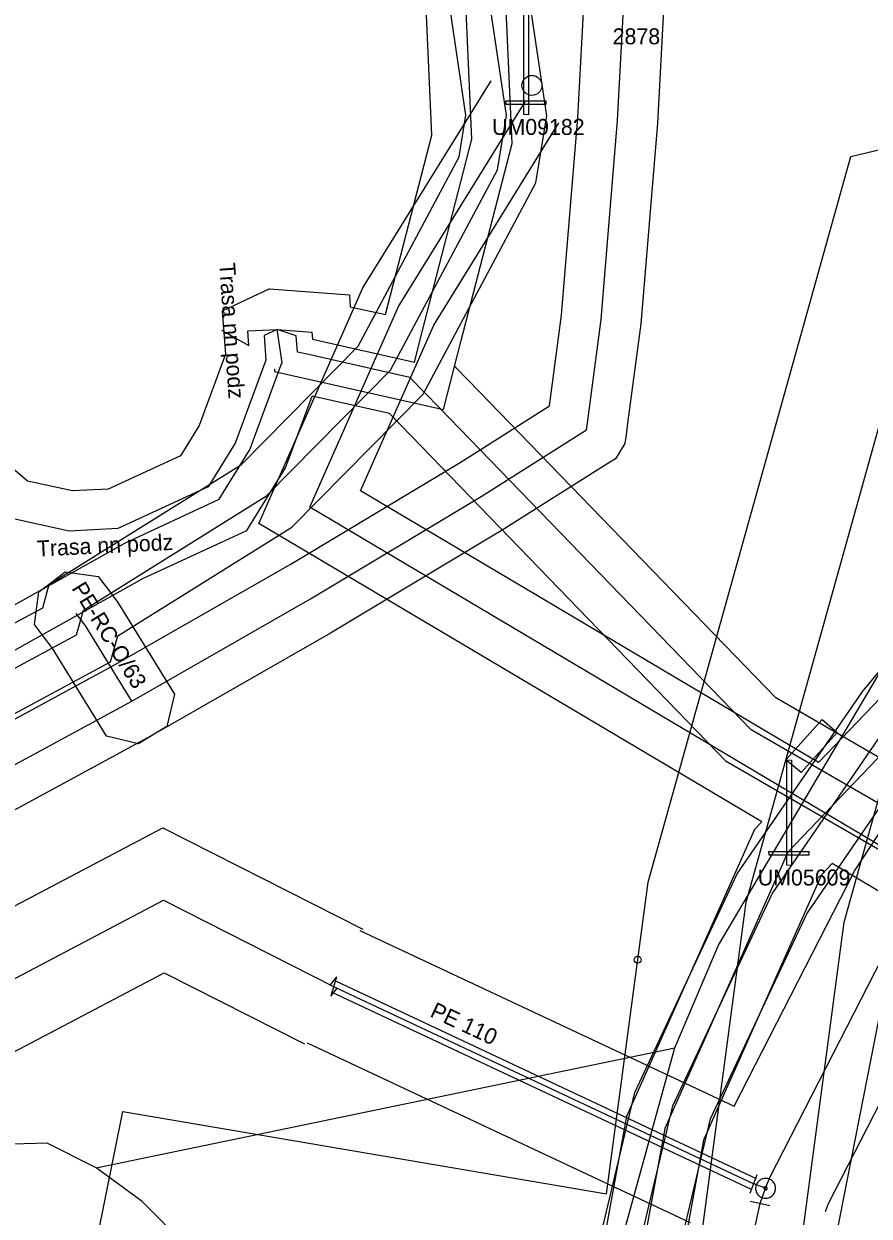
# Model space of a CAD drawing. Extents: x -762993 to -761845, y -975230 to -974501.
# Drawn here: x -762318.78 to -762297.6, y -975033.65 to -975003.77 of the extents above; entities that cross this region are included whole.
import ezdxf

# ---------------------------------------------------------------- set-up
doc = ezdxf.new("R2010")
doc.units = 0
for name, color, linetype in [('IS_CETIN_OP', 7, 'Continuous'), ('IS_CETIN_podzem metalika zam', 7, 'Continuous'), ('IS_CETIN_podzem out of order', 7, 'Continuous'), ('IS_CEZ-D_anotace', 7, 'Continuous'), ('IS_CEZ-D_el vedeni NN podzem', 7, 'Continuous'), ('IS_CEZ-D_OP', 7, 'Continuous'), ('IS_CEZ-T_parovod', 7, 'Continuous'), ('IS_CEZ-T_parovod OP', 7, 'Continuous'), ('IS_DPmUL_OP', 7, 'Continuous'), ('IS_DPmUL_trakce anotace', 7, 'Continuous'), ('IS_DPmUL_trakce stozary', 7, 'Continuous'), ('IS_DPmUL_VO lampy', 7, 'Continuous'), ('IS_DPmUL_VO lampy anotace', 7, 'Continuous'), ('IS_DPmUL_VO vedeni podzem', 7, 'Continuous'), ('IS_GASNET_plyn NTL anotace', 7, 'Continuous'), ('IS_GASNET_plyn NTL pripojky', 7, 'Continuous'), ('IS_GASNET_plyn NTL rad', 7, 'Continuous'), ('IS_GASNET_plyn OP', 7, 'Continuous'), ('IS_SCVK_vodovod anotace', 7, 'Continuous'), ('IS_SCVK_vodovod chranicka', 7, 'Continuous'), ('IS_SCVK_vodovod OP', 7, 'Continuous'), ('IS_SCVK_vodovod privadec', 7, 'Continuous'), ('IS_SCVK_vodovod znaky', 7, 'Continuous'), ('IS_T-Mobile_OP', 7, 'Continuous'), ('IS_T-Mobile_podzem optika', 7, 'Continuous')]:
    doc.layers.add(name, color=color, linetype=linetype)

msp = doc.modelspace()

# ---------------------------------------------------------------- linework, layer by layer
at = {"layer": 'IS_CETIN_OP'}
for points in [[(-762333.143, -975068.542), (-762327.185, -975070.257), (-762325.869, -975070.135), (-762319.571, -975070.861), (-762312.657, -975072.148), (-762308.168, -975050.829), (-762306.083, -975041.38), (-762305.481, -975039.001), (-762303.469, -975030.548), (-762300.901, -975025.071), (-762297.758, -975020.495), (-762293.905, -975015.874), (-762285.788, -975009.313), (-762278.568, -975006.279), (-762273.774, -975005.065), (-762267.42, -975003.752), (-762256.598, -975003.579), (-762252.471, -975004.243)], [(-762333.697, -975070.464), (-762327.375, -975072.283), (-762325.891, -975072.145), (-762319.869, -975072.839), (-762311.103, -975074.472), (-762306.212, -975051.251), (-762304.137, -975041.84), (-762303.539, -975039.479), (-762301.571, -975031.212), (-762299.159, -975026.069), (-762296.162, -975021.705), (-762292.495, -975017.306), (-762284.752, -975011.047), (-762277.932, -975008.181), (-762273.326, -975007.015), (-762267.2, -975005.748), (-762256.742, -975005.581), (-762252.789, -975006.217)]]:
    msp.add_lwpolyline(points, dxfattribs=at)
at = {"layer": 'IS_CETIN_podzem metalika zam'}
msp.add_lwpolyline([(-762333.42, -975069.503), (-762327.28, -975071.27), (-762325.88, -975071.14), (-762319.72, -975071.85), (-762311.88, -975073.31), (-762307.19, -975051.04), (-762305.11, -975041.61), (-762304.51, -975039.24), (-762302.52, -975030.88), (-762300.03, -975025.57), (-762296.96, -975021.1), (-762293.2, -975016.59), (-762285.27, -975010.18), (-762278.25, -975007.23), (-762273.55, -975006.04), (-762267.31, -975004.75), (-762256.67, -975004.58), (-762252.63, -975005.23)], dxfattribs=at)
at = {"layer": 'IS_CETIN_podzem out of order'}
for points in [[(-762302.47, -975029.43), (-762301.37, -975026.86), (-762297.29, -975019.96), (-762293.71, -975015.73), (-762290.26, -975012.31), (-762286.4, -975009.38), (-762280.32, -975006.03), (-762275.63, -975004.71), (-762266.26, -975003.66), (-762260.97, -975004.16), (-762250.2, -975005.66)], [(-762314.94, -975039.44), (-762305.75, -975041.48), (-762300.55, -975042.65), (-762300.16, -975040.36), (-762298.53, -975034.72), (-762296.75, -975025.67), (-762290.69, -975018.58), (-762286.29, -975015.28), (-762283.37, -975012.48), (-762276.83, -975008.96), (-762270.07, -975007.94), (-762262.86, -975007.55), (-762258.26, -975007.97), (-762258.37, -975010.02)], [(-762316.97, -975032.44), (-762302.47, -975029.43)], [(-762314.72, -975038.47), (-762313.26, -975038.76), (-762305.52, -975040.49), (-762302.47, -975029.43)], [(-762316.97, -975032.44), (-762318.2, -975031.82), (-762319.64, -975031.86), (-762321.84, -975032.66), (-762325.75, -975034.84), (-762334.32, -975039.88), (-762342.38, -975044.44), (-762350.45, -975049.19)], [(-762314.72, -975038.47), (-762314.35, -975036), (-762314.74, -975034.37), (-762315.82, -975033.28), (-762316.97, -975032.44)]]:
    msp.add_lwpolyline(points, dxfattribs=at)
at = {"layer": 'IS_CEZ-D_el vedeni NN podzem'}
for points in [[(-762312.434, -975011.429), (-762311.562, -975011.492), (-762311.55, -975011.669), (-762308.991, -975012.245), (-762308.787, -975011.452), (-762307.552, -975006.66), (-762307.854, -974999.844), (-762312.234, -974993.249), (-762317.513, -974989.187), (-762333.367, -974983.038), (-762339.038, -974981.25), (-762354.832, -974975.823), (-762355.035, -974975.753), (-762355.226, -974976.23), (-762356.629, -974979.736), (-762357.615, -974982.215), (-762357.804, -974982.149)], [(-762323.24, -975032.631), (-762327.897, -975023.324), (-762326.508, -975022.51), (-762316.256, -975016.781), (-762313.888, -975015.684), (-762313.128, -975014.455), (-762313.114, -975014.417), (-762312.341, -975012.334), (-762312.311, -975012.253), (-762312.434, -975011.429)], [(-762312.434, -975011.429), (-762312.761, -975011.582), (-762312.716, -975012.195), (-762313.489, -975014.278), (-762314.166, -975015.372), (-762316.424, -975016.419), (-762317.643, -975016.479), (-762319.16, -975016.149), (-762319.611, -975015.754), (-762320.71, -975014.965), (-762320.816, -975013.314), (-762320.212, -975013.263), (-762320.229, -975013.064)], [(-762313.829, -975011.448), (-762313.143, -975011.83), (-762313.169, -975011.461), (-762312.434, -975011.429)], [(-762266.642, -975017.146), (-762269.935, -975017.363), (-762272.799, -975018.022), (-762274.441, -975018.54), (-762276.825, -975019.952), (-762278.883, -975021.862), (-762280.371, -975023.677), (-762281.857, -975025.781), (-762283.232, -975030.127), (-762294.247, -975025.106), (-762300.557, -975021.459), (-762308.359, -975013.401), (-762309.107, -975012.628), (-762311.684, -975012.049), (-762311.927, -975011.994), (-762311.958, -975011.586), (-762312.434, -975011.429)]]:
    msp.add_lwpolyline(points, dxfattribs=at)
at = {"layer": 'IS_CEZ-D_OP'}
for points in [[(-762312.622, -975010.413), (-762310.623, -975010.557), (-762310.603, -975010.857), (-762309.718, -975011.056), (-762308.558, -975006.555), (-762308.841, -975000.166), (-762312.975, -974993.94), (-762318.009, -974990.067), (-762333.698, -974983.982), (-762339.351, -974982.2), (-762354.46, -974977.008), (-762355.7, -974980.107), (-762357.04, -974983.475), (-762358.93, -974982.815)], [(-762312.506, -975012.426), (-762312.501, -975012.427), (-762312.497, -975012.481), (-762308.264, -975013.434), (-762307.819, -975011.701), (-762306.546, -975006.765), (-762306.867, -974999.522), (-762311.493, -974992.558), (-762311.896, -974992.247)], [(-762312.622, -975010.413), (-762313.809, -975010.968), (-762313.729, -975012.051), (-762314.392, -975013.837), (-762314.859, -975014.591), (-762316.668, -975015.43), (-762317.56, -975015.474), (-762318.695, -975015.227), (-762318.989, -975014.97), (-762319.742, -975014.429), (-762319.755, -975014.228), (-762319.13, -975014.175), (-762319.233, -975012.979)], [(-762210.784, -975019.48), (-762216.14, -975019.152), (-762233.918, -975018.301), (-762252.803, -975016.92), (-762257.758, -975016.55), (-762262.733, -975016.178), (-762264.701, -975016.162), (-762266.671, -975016.146), (-762270.081, -975016.37), (-762273.062, -975017.056), (-762274.852, -975017.621), (-762277.427, -975019.146), (-762279.613, -975021.175), (-762281.167, -975023.071), (-762282.764, -975025.331), (-762283.845, -975028.749), (-762293.788, -975024.216), (-762299.936, -975020.663), (-762307.64, -975012.706), (-762307.985, -975012.349)], [(-762321.902, -975033.07), (-762326.584, -975023.714), (-762326.011, -975023.378), (-762315.801, -975017.672), (-762313.195, -975016.465), (-762312.224, -975014.895), (-762312.176, -975014.764), (-762311.559, -975013.102)], [(-762209.615, -975021.555), (-762216.248, -975021.15), (-762234.038, -975020.297), (-762252.951, -975018.914), (-762257.906, -975018.544), (-762262.815, -975018.178), (-762264.717, -975018.162), (-762266.613, -975018.146), (-762269.789, -975018.356), (-762272.536, -975018.988), (-762274.03, -975019.459), (-762276.223, -975020.758), (-762278.153, -975022.549), (-762279.575, -975024.283), (-762280.95, -975026.231), (-762282.619, -975031.505), (-762294.706, -975025.996), (-762301.178, -975022.255), (-762309.078, -975014.096), (-762309.618, -975013.538), (-762311.559, -975013.102)]]:
    msp.add_lwpolyline(points, dxfattribs=at)
at = {"layer": 'IS_CEZ-T_parovod'}
for points in [[(-762300.68, -975025.78), (-762296.04, -975009.18), (-762277.86, -975004.82)], [(-762319.25, -975058.25), (-762314.33, -975033.9), (-762302.04, -975035.99), (-762300.68, -975025.78)]]:
    msp.add_lwpolyline(points, dxfattribs=at)
at = {"layer": 'IS_CEZ-T_parovod OP'}
for points in [[(-762303.135, -975025.276), (-762298.052, -975007.092), (-762280.855, -975002.967)], [(-762298.225, -975026.284), (-762294.028, -975011.268), (-762278.275, -975007.49)], [(-762321.7, -975057.755), (-762316.3, -975031.029), (-762304.176, -975033.091), (-762303.135, -975025.276)], [(-762316.8, -975058.745), (-762312.36, -975036.771), (-762299.904, -975038.889), (-762298.225, -975026.284)]]:
    msp.add_lwpolyline(points, dxfattribs=at)
at = {"layer": 'IS_DPmUL_OP'}
for p, q in [((-762286.053, -975008.896), (-762298.867, -975022.284)), ((-762300.286, -975023.767), (-762300.474, -975023.963)), ((-762298.521, -975024.815), (-762298.788, -975025.095))]:
    msp.add_line(p, q, dxfattribs=at)
for points in [[(-762300.286, -975023.767), (-762312.892, -975016.287), (-762310.283, -975010.386), (-762307.071, -975005.194)], [(-762298.867, -975022.284), (-762310.346, -975015.473), (-762308.509, -975011.32), (-762305.371, -975006.246)], [(-762300.474, -975023.963), (-762303.676, -975031.15), (-762308.683, -975058.513)], [(-762288.852, -975032.788), (-762292.269, -975030.584), (-762294.745, -975027.055), (-762298.521, -975024.815)], [(-762298.788, -975025.095), (-762301.752, -975031.746), (-762306.715, -975058.873)]]:
    msp.add_lwpolyline(points, dxfattribs=at)
at = {"layer": 'IS_DPmUL_trakce stozary'}
for centre, radius in [((-762306.048, -975005.313), 0.25), ((-762303.398, -975027.223), 0.0875)]:
    msp.add_circle(centre, radius, dxfattribs=at)
at = {"layer": 'IS_DPmUL_VO lampy'}
for points in [[(-762306.251, -975003.4), (-762306.131, -975003.41), (-762306.131, -975006.05), (-762306.251, -975006.04)], [(-762306.701, -975005.7), (-762305.701, -975005.7), (-762305.701, -975005.79), (-762306.691, -975005.79)], [(-762298.771, -975021.199), (-762298.401, -975021.529), (-762299.301, -975022.529), (-762299.681, -975022.209)], [(-762299.661, -975022.209), (-762299.541, -975022.219), (-762299.541, -975024.859), (-762299.661, -975024.849)], [(-762300.111, -975024.509), (-762299.111, -975024.509), (-762299.111, -975024.599), (-762300.101, -975024.599)]]:
    msp.add_lwpolyline(points, close=True, dxfattribs=at)
at = {"layer": 'IS_DPmUL_VO vedeni podzem'}
for points in [[(-762248.64, -975011.03), (-762256.056, -975014.399), (-762265.581, -975014.505), (-762271.667, -975016.41), (-762273.519, -975019.955), (-762287.542, -975032.443), (-762291.563, -975029.85), (-762294.05, -975026.305), (-762311.619, -975015.88), (-762309.396, -975010.853), (-762306.221, -975005.72)], [(-762285.478, -975009.742), (-762299.631, -975024.529)], [(-762299.631, -975024.529), (-762302.714, -975031.448), (-762307.699, -975058.693)]]:
    msp.add_lwpolyline(points, dxfattribs=at)
at = {"layer": 'IS_GASNET_plyn NTL pripojky'}
msp.add_lwpolyline([(-762316.08, -975020.74), (-762317.25, -975018.84), (-762317.47, -975018.55)], dxfattribs=at)
at = {"layer": 'IS_GASNET_plyn NTL rad'}
msp.add_lwpolyline([(-762382.14, -975056.56), (-762374.12, -975052.41), (-762369.1, -975049.66), (-762366.32, -975048.11), (-762358.1, -975043.65), (-762340.31, -975033.92), (-762334.72, -975030.54), (-762325.49, -975025.85), (-762316.08, -975020.74), (-762311.6, -975018.18), (-762307.32, -975015.61), (-762304.68, -975013.94), (-762304.65, -975013.71), (-762304.31, -975011.18), (-762303.9, -975006.19), (-762303.47, -974998.11), (-762299.684, -974994.021), (-762299.23, -974993.53)], dxfattribs=at)
at = {"layer": 'IS_GASNET_plyn OP'}
for points in [[(-762382.6, -975055.672), (-762374.59, -975051.527), (-762369.584, -975048.785), (-762366.802, -975047.234), (-762358.578, -975042.772), (-762340.809, -975033.053), (-762335.206, -975029.665), (-762325.955, -975024.965), (-762316.567, -975019.866), (-762312.106, -975017.317), (-762307.845, -975014.759), (-762305.61, -975013.345), (-762305.305, -975011.072), (-762304.898, -975006.122), (-762304.449, -974997.696)], [(-762302.491, -974998.524), (-762302.902, -975006.258), (-762303.315, -975011.288), (-762303.659, -975013.841), (-762303.688, -975014.069), (-762303.717, -975014.29), (-762303.957, -975014.666), (-762304.145, -975014.785), (-762306.795, -975016.461), (-762311.094, -975019.043), (-762315.593, -975021.614), (-762325.025, -975026.735), (-762334.234, -975031.415), (-762339.811, -975034.787), (-762357.622, -975044.528), (-762365.838, -975048.986), (-762368.616, -975050.535), (-762373.65, -975053.293), (-762381.68, -975057.448)]]:
    msp.add_lwpolyline(points, dxfattribs=at)
msp.add_lwpolyline([(-762316.715, -975021.617), (-762316.932, -975021.264), (-762318.076, -975019.406), (-762318.267, -975019.154), (-762318.517, -975018.824), (-762318.404, -975018.004), (-762318.074, -975017.753), (-762317.744, -975017.503), (-762316.924, -975017.616), (-762316.673, -975017.946), (-762316.424, -975018.274), (-762315.228, -975020.216), (-762315.011, -975020.568), (-762315.203, -975021.375), (-762315.556, -975021.592), (-762315.908, -975021.809)], close=True, dxfattribs=at)
at = {"layer": 'IS_SCVK_vodovod chranicka'}
for points in [[(-762310.955, -975027.758), (-762300.424, -975032.704)], [(-762311.083, -975028.03), (-762300.552, -975032.976)]]:
    msp.add_lwpolyline(points, dxfattribs=at)
at = {"layer": 'IS_SCVK_vodovod OP'}
for p, q in [((-762310.358, -975026.487), (-762300.983, -975030.89)), ((-762311.68, -975029.301), (-762302.084, -975033.808))]:
    msp.add_line(p, q, dxfattribs=at)
for points in [[(-762300.983, -975030.89), (-762297.958, -975024.984), (-762295.528, -975021.282), (-762290.667, -975015.916), (-762284.106, -975010.718), (-762280.993, -975009.206), (-762277.378, -975007.772)], [(-762298.687, -975033.531), (-762298.612, -975033.335), (-762295.166, -975026.608), (-762292.97, -975023.262), (-762288.455, -975018.278), (-762282.38, -975013.464), (-762279.693, -975012.16), (-762276.236, -975010.788), (-762275.358, -975010.572)], [(-762328.311, -975030.77), (-762315.298, -975023.919), (-762310.29, -975026.455)], [(-762326.809, -975033.624), (-762315.27, -975027.549), (-762311.748, -975029.333)]]:
    msp.add_lwpolyline(points, dxfattribs=at)
at = {"layer": 'IS_SCVK_vodovod privadec'}
for points in [[(-762300.192, -975032.951), (-762300.086, -975032.676), (-762296.562, -975025.796), (-762294.249, -975022.272), (-762289.561, -975017.097), (-762283.243, -975012.091), (-762280.343, -975010.683), (-762276.729, -975009.249), (-762275.744, -975009.006)], [(-762327.56, -975032.197), (-762315.284, -975025.734), (-762311.019, -975027.894)], [(-762311.019, -975027.894), (-762300.488, -975032.84)], [(-762309.975, -975078.071), (-762306.855, -975063.21), (-762300.329, -975033.329)]]:
    msp.add_lwpolyline(points, dxfattribs=at)
at = {"layer": 'IS_SCVK_vodovod znaky'}
for points in [[(-762310.949, -975027.649), (-762311.109, -975027.849)], [(-762310.949, -975027.649), (-762311.088, -975028.139)], [(-762311.088, -975028.139), (-762310.929, -975027.939)], [(-762300.576, -975033.074), (-762300.4, -975032.606)], [(-762300.192, -975032.951), (-762300.488, -975032.84)], [(-762300.106, -975032.716), (-762300.132, -975032.709), (-762300.157, -975032.703), (-762300.183, -975032.701), (-762300.209, -975032.702), (-762300.236, -975032.704), (-762300.261, -975032.711), (-762300.285, -975032.72), (-762300.309, -975032.731), (-762300.332, -975032.744), (-762300.353, -975032.76), (-762300.372, -975032.778), (-762300.389, -975032.798), (-762300.404, -975032.819), (-762300.417, -975032.842), (-762300.427, -975032.866), (-762300.434, -975032.891), (-762300.439, -975032.916), (-762300.442, -975032.943), (-762300.441, -975032.968), (-762300.438, -975032.995), (-762300.432, -975033.02), (-762300.424, -975033.045), (-762300.412, -975033.069), (-762300.399, -975033.091), (-762300.383, -975033.111), (-762300.365, -975033.131), (-762300.346, -975033.148), (-762300.324, -975033.163), (-762300.301, -975033.176), (-762300.277, -975033.186), (-762300.252, -975033.193), (-762300.226, -975033.199), (-762300.2, -975033.201), (-762300.175, -975033.2), (-762300.148, -975033.197), (-762300.123, -975033.192), (-762300.098, -975033.183), (-762300.074, -975033.172), (-762300.052, -975033.158), (-762300.031, -975033.142), (-762300.012, -975033.124), (-762299.995, -975033.105), (-762299.98, -975033.083), (-762299.967, -975033.06), (-762299.957, -975033.036), (-762299.949, -975033.011), (-762299.944, -975032.986), (-762299.942, -975032.959), (-762299.943, -975032.934), (-762299.946, -975032.907), (-762299.951, -975032.882), (-762299.96, -975032.858), (-762299.971, -975032.834), (-762299.985, -975032.811), (-762300.001, -975032.79), (-762300.019, -975032.771), (-762300.038, -975032.754), (-762300.06, -975032.739), (-762300.083, -975032.726), (-762300.106, -975032.716)], [(-762300.178, -975032.912), (-762300.182, -975032.91), (-762300.186, -975032.91), (-762300.19, -975032.91), (-762300.194, -975032.91), (-762300.199, -975032.91), (-762300.203, -975032.912), (-762300.207, -975032.913), (-762300.211, -975032.915), (-762300.215, -975032.917), (-762300.218, -975032.92), (-762300.221, -975032.923), (-762300.224, -975032.926), (-762300.226, -975032.929), (-762300.229, -975032.932), (-762300.231, -975032.937), (-762300.232, -975032.941), (-762300.232, -975032.945), (-762300.233, -975032.949), (-762300.233, -975032.954), (-762300.232, -975032.958), (-762300.231, -975032.962), (-762300.23, -975032.966), (-762300.228, -975032.97), (-762300.226, -975032.974), (-762300.223, -975032.977), (-762300.22, -975032.981), (-762300.217, -975032.983), (-762300.214, -975032.986), (-762300.21, -975032.988), (-762300.206, -975032.99), (-762300.202, -975032.991), (-762300.198, -975032.991), (-762300.194, -975032.992), (-762300.189, -975032.992), (-762300.185, -975032.991), (-762300.181, -975032.991), (-762300.177, -975032.989), (-762300.172, -975032.987), (-762300.169, -975032.985), (-762300.166, -975032.982), (-762300.162, -975032.979), (-762300.16, -975032.976), (-762300.157, -975032.973), (-762300.155, -975032.969), (-762300.153, -975032.965), (-762300.152, -975032.961), (-762300.152, -975032.957), (-762300.151, -975032.953), (-762300.151, -975032.948), (-762300.152, -975032.944), (-762300.152, -975032.94), (-762300.154, -975032.936), (-762300.155, -975032.932), (-762300.158, -975032.928), (-762300.16, -975032.925), (-762300.164, -975032.921), (-762300.167, -975032.919), (-762300.17, -975032.916), (-762300.174, -975032.914), (-762300.178, -975032.912)], [(-762300.329, -975033.329), (-762300.192, -975032.951)], [(-762300.573, -975033.275), (-762300.084, -975033.383)]]:
    msp.add_lwpolyline(points, dxfattribs=at)
at = {"layer": 'IS_T-Mobile_OP'}
for p, q in [((-762305.677, -975006.076), (-762306.298, -975001.884)), ((-762307.701, -975006.062), (-762308.262, -975002.274)), ((-762307.87, -975007.106), (-762307.701, -975006.062)), ((-762305.95, -975007.754), (-762305.677, -975006.076)), ((-762310.404, -975011.85), (-762307.87, -975007.106)), ((-762308.776, -975013.048), (-762305.95, -975007.754)), ((-762313.328, -975014.814), (-762310.404, -975011.85)), ((-762312.07, -975016.386), (-762308.776, -975013.048)), ((-762318.151, -975017.818), (-762313.328, -975014.814)), ((-762316.429, -975019.102), (-762312.07, -975016.386)), ((-762318.311, -975018.402), (-762318.151, -975017.818)), ((-762323.044, -975020.96), (-762318.311, -975018.402)), ((-762316.609, -975019.756), (-762316.429, -975019.102)), ((-762322.094, -975022.72), (-762316.609, -975019.756))]:
    msp.add_line(p, q, dxfattribs=at)
at = {"layer": 'IS_T-Mobile_podzem optika'}
for points in [[(-762306.689, -975006.069), (-762307.28, -975002.079)], [(-762306.689, -975006.069), (-762307.28, -975002.079)], [(-762306.91, -975007.43), (-762306.689, -975006.069)], [(-762306.91, -975007.43), (-762306.689, -975006.069)], [(-762309.59, -975012.449), (-762306.91, -975007.43)], [(-762309.59, -975012.449), (-762306.91, -975007.43)], [(-762312.699, -975015.6), (-762309.59, -975012.449)], [(-762312.699, -975015.6), (-762309.59, -975012.449)], [(-762317.29, -975018.46), (-762312.699, -975015.6)], [(-762317.29, -975018.46), (-762312.699, -975015.6)], [(-762317.46, -975019.079), (-762317.29, -975018.46)], [(-762317.46, -975019.079), (-762317.29, -975018.46)], [(-762322.569, -975021.84), (-762317.46, -975019.079)], [(-762322.569, -975021.84), (-762317.46, -975019.079)]]:
    msp.add_lwpolyline(points, dxfattribs=at)

# ---------------------------------------------------------------- texts
at = {"layer": 'IS_CEZ-D_anotace'}
for rotation, p in [(274.0304, (-762313.889, -975009.768)), (2.8179, (-762318.447, -975017.12))]:
    msp.add_text('Trasa nn podz', height=0.4, rotation=rotation, dxfattribs=at).set_placement(p)
at = {"layer": 'IS_DPmUL_trakce anotace'}
msp.add_text('2878', height=0.4, dxfattribs=at).set_placement((-762304.025, -975004.282))
at = {"layer": 'IS_DPmUL_VO lampy anotace'}
for s, p in [('UM09182', (-762307.047, -975006.553)), ('UM05609', (-762300.387, -975025.362))]:
    msp.add_text(s, height=0.4, dxfattribs=at).set_placement(p)
at = {"layer": 'IS_GASNET_plyn NTL anotace'}
msp.add_text('PE-RC-O/63', height=0.4, rotation=301.6243, dxfattribs=at).set_placement((-762317.598, -975017.914))
at = {"layer": 'IS_SCVK_vodovod anotace'}
msp.add_text('PE 110', height=0.4, rotation=335, dxfattribs=at).set_placement((-762308.627, -975028.635))

doc.saveas('drawing.dxf')
